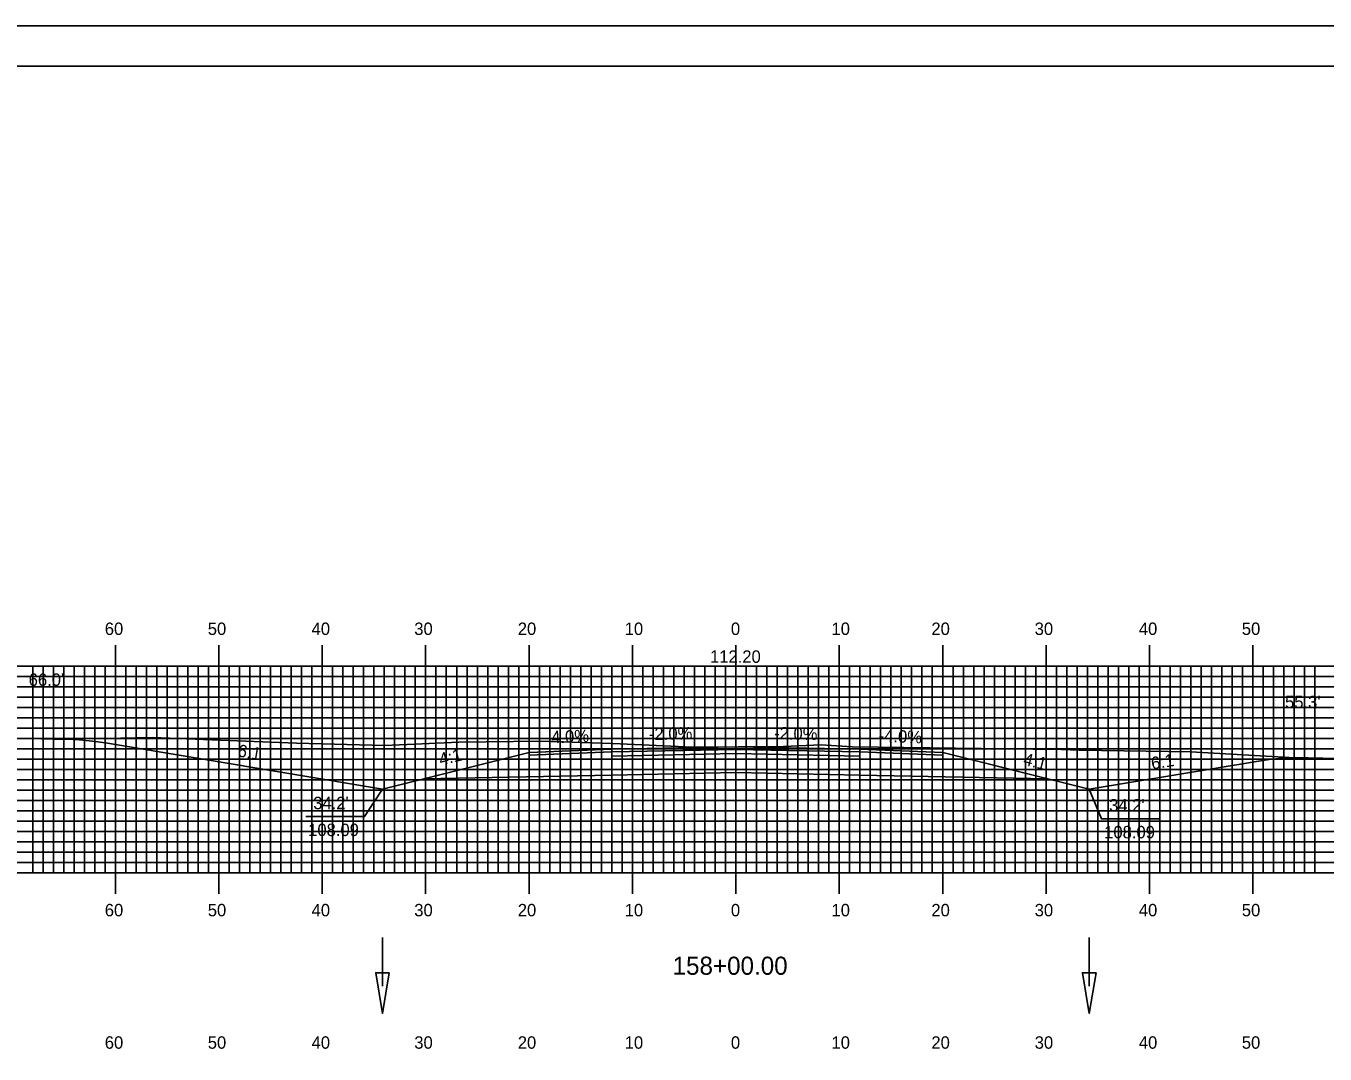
# Model space of a CAD drawing. Extents: x 1779499 to 1779842, y 442591 to 442811.
# Drawn here: x 1779596.2 to 1779721.8, y 442711.2 to 442810.5 of the extents above; entities that cross this region are included whole.
import ezdxf

# ---------------------------------------------------------------- set-up
doc = ezdxf.new("R2010")
doc.units = 0
for name, color, linetype in [('ANNOTATION', 7, 'Continuous'), ('BORDER', 7, 'Continuous'), ('D_Drainage_Ditch_Line', 7, 'Continuous'), ('D_Roadway_Centerline', 7, 'Continuous'), ('D_Roadway_Centerline_Text', 7, 'Continuous'), ('D_Roadway_Edge_Shoulder', 7, 'Continuous'), ('D_Roadway_Edge_TW', 7, 'Continuous'), ('D_Roadway_Pavement', 7, 'Continuous'), ('D_Roadway_SlopeLines', 7, 'Continuous'), ('D_Roadway_SubGrade', 7, 'Continuous'), ('D_Text_Standard', 7, 'Continuous'), ('H_V ANNOTATION', 7, 'Continuous'), ('MAJOR', 7, 'Continuous'), ('MINOR', 7, 'Continuous'), ('PLOT BOUNDARY', 7, 'Continuous'), ('S_Roadway_Centerline', 7, 'Continuous')]:
    doc.layers.add(name, color=color, linetype=linetype)

msp = doc.modelspace()

# ---------------------------------------------------------------- linework, layer by layer
at = {"layer": 'ANNOTATION'}
for points in [[(1779623.24, 442734.11), (1779628.93, 442734.11), (1779630.67, 442736.76)], [(1779705.9, 442733.88), (1779700.21, 442733.88), (1779699.02, 442736.76)]]:
    msp.add_lwpolyline(points, dxfattribs=at)
at = {"layer": 'BORDER'}
msp.add_lwpolyline([(1779515.24, 442596.67), (1779835.24, 442596.67), (1779835.24, 442806.67), (1779515.24, 442806.67)], close=True, dxfattribs=at)
at = {"layer": 'D_Drainage_Ditch_Line'}
for p, q in [((1779630.67, 442717.71), (1779630.67, 442722.41)), ((1779699.02, 442717.71), (1779699.02, 442722.41))]:
    msp.add_line(p, q, dxfattribs=at)
for points in [[(1779631.32, 442719.02), (1779630.01, 442719.02), (1779630.67, 442715.09)], [(1779699.67, 442719.02), (1779698.36, 442719.02), (1779699.02, 442715.09)]]:
    msp.add_lwpolyline(points, close=True, dxfattribs=at)
at = {"layer": 'D_Roadway_Centerline'}
msp.add_lwpolyline([(1779598.87, 442741.61), (1779600.12, 442741.6), (1779601.37, 442741.53), (1779602.62, 442741.41), (1779603.87, 442741.23), (1779630.67, 442736.76), (1779634.67, 442737.76), (1779644.84, 442740.3), (1779652.84, 442740.62), (1779664.84, 442740.86), (1779676.84, 442740.62), (1779684.84, 442740.3), (1779695.02, 442737.76), (1779699.02, 442736.76), (1779715.18, 442739.45), (1779716.43, 442739.63), (1779717.68, 442739.75), (1779718.93, 442739.8), (1779720.18, 442739.79)], dxfattribs=at)
at = {"layer": 'D_Roadway_Edge_Shoulder'}
for points in [[(1779652.84, 442740.62), (1779644.84, 442740.3), (1779644.84, 442740.05), (1779652.84, 442740.37)], [(1779676.84, 442740.62), (1779684.84, 442740.3), (1779684.84, 442740.05), (1779676.84, 442740.37)]]:
    msp.add_lwpolyline(points, close=True, dxfattribs=at)
at = {"layer": 'D_Roadway_Edge_TW'}
msp.add_lwpolyline([(1779652.84, 442740.37), (1779652.84, 442740.62), (1779664.84, 442740.86), (1779676.84, 442740.62), (1779676.84, 442740.37), (1779664.84, 442740.61)], close=True, dxfattribs=at)
at = {"layer": 'D_Roadway_Pavement'}
msp.add_lwpolyline([(1779652.84, 442739.96), (1779652.84, 442740.37), (1779664.84, 442740.61), (1779676.84, 442740.37), (1779676.84, 442739.96), (1779664.84, 442740.2)], close=True, dxfattribs=at)
at = {"layer": 'D_Roadway_SlopeLines'}
for points in [[(1779630.67, 442736.76), (1779603.87, 442741.23), (1779602.62, 442741.41), (1779601.37, 442741.53), (1779600.12, 442741.6), (1779598.87, 442741.61)], [(1779644.84, 442740.3), (1779630.67, 442736.76)], [(1779684.84, 442740.3), (1779699.02, 442736.76)], [(1779699.02, 442736.76), (1779715.18, 442739.45), (1779716.43, 442739.63), (1779717.68, 442739.75), (1779718.93, 442739.8), (1779720.18, 442739.79)]]:
    msp.add_lwpolyline(points, dxfattribs=at)
at = {"layer": 'D_Roadway_SubGrade'}
msp.add_lwpolyline([(1779652.84, 442738.12), (1779634.67, 442737.76), (1779644.84, 442740.3), (1779644.84, 442740.05), (1779652.84, 442740.37), (1779664.84, 442740.61), (1779676.84, 442740.37), (1779684.84, 442740.05), (1779684.84, 442740.3), (1779695.02, 442737.76), (1779676.84, 442738.12), (1779664.84, 442738.36)], close=True, dxfattribs=at)
at = {"layer": 'MAJOR'}
for p, q in [((1779604.84, 442750.67), (1779604.84, 442748.67)), ((1779614.84, 442750.67), (1779614.84, 442748.67)), ((1779624.84, 442750.67), (1779624.84, 442748.67)), ((1779634.84, 442750.67), (1779634.84, 442748.67)), ((1779644.84, 442750.67), (1779644.84, 442748.67)), ((1779654.84, 442750.67), (1779654.84, 442748.67)), ((1779664.84, 442750.67), (1779664.84, 442748.67)), ((1779674.84, 442750.67), (1779674.84, 442748.67)), ((1779684.84, 442750.67), (1779684.84, 442748.67)), ((1779694.84, 442750.67), (1779694.84, 442748.67)), ((1779704.84, 442750.67), (1779704.84, 442748.67)), ((1779714.84, 442750.67), (1779714.84, 442748.67)), ((1779524.84, 442748.67), (1779804.84, 442748.67)), ((1779524.84, 442748.67), (1779804.84, 442748.67)), ((1779604.84, 442728.67), (1779604.84, 442748.67)), ((1779614.84, 442728.67), (1779614.84, 442748.67)), ((1779624.84, 442728.67), (1779624.84, 442748.67)), ((1779634.84, 442728.67), (1779634.84, 442748.67)), ((1779644.84, 442728.67), (1779644.84, 442748.67)), ((1779654.84, 442728.67), (1779654.84, 442748.67)), ((1779664.84, 442728.67), (1779664.84, 442748.67)), ((1779674.84, 442728.67), (1779674.84, 442748.67)), ((1779684.84, 442728.67), (1779684.84, 442748.67)), ((1779694.84, 442728.67), (1779694.84, 442748.67)), ((1779704.84, 442728.67), (1779704.84, 442748.67)), ((1779714.84, 442728.67), (1779714.84, 442748.67)), ((1779524.84, 442743.67), (1779804.84, 442743.67)), ((1779524.84, 442738.67), (1779804.84, 442738.67)), ((1779524.84, 442733.67), (1779804.84, 442733.67)), ((1779524.84, 442728.67), (1779804.84, 442728.67)), ((1779524.84, 442728.67), (1779804.84, 442728.67)), ((1779604.84, 442726.66), (1779604.84, 442728.67)), ((1779614.84, 442726.66), (1779614.84, 442728.67)), ((1779624.84, 442726.66), (1779624.84, 442728.67)), ((1779634.84, 442726.66), (1779634.84, 442728.67)), ((1779644.84, 442726.66), (1779644.84, 442728.67)), ((1779654.84, 442726.66), (1779654.84, 442728.67)), ((1779664.84, 442726.66), (1779664.84, 442728.67)), ((1779674.84, 442726.66), (1779674.84, 442728.67)), ((1779684.84, 442726.66), (1779684.84, 442728.67)), ((1779694.84, 442726.66), (1779694.84, 442728.67)), ((1779704.84, 442726.66), (1779704.84, 442728.67)), ((1779714.84, 442726.66), (1779714.84, 442728.67))]:
    msp.add_line(p, q, dxfattribs=at)
at = {"layer": 'MINOR'}
for p, q in [((1779524.84, 442747.67), (1779804.84, 442747.67)), ((1779596.84, 442728.67), (1779596.84, 442748.67)), ((1779597.84, 442728.67), (1779597.84, 442748.67)), ((1779598.84, 442728.67), (1779598.84, 442748.67)), ((1779599.84, 442728.67), (1779599.84, 442748.67)), ((1779600.84, 442728.67), (1779600.84, 442748.67)), ((1779601.84, 442728.67), (1779601.84, 442748.67)), ((1779602.84, 442728.67), (1779602.84, 442748.67)), ((1779603.84, 442728.67), (1779603.84, 442748.67)), ((1779605.84, 442728.67), (1779605.84, 442748.67)), ((1779606.84, 442728.67), (1779606.84, 442748.67)), ((1779607.84, 442728.67), (1779607.84, 442748.67)), ((1779608.84, 442728.67), (1779608.84, 442748.67)), ((1779609.84, 442728.67), (1779609.84, 442748.67)), ((1779610.84, 442728.67), (1779610.84, 442748.67)), ((1779611.84, 442728.67), (1779611.84, 442748.67)), ((1779612.84, 442728.67), (1779612.84, 442748.67)), ((1779613.84, 442728.67), (1779613.84, 442748.67)), ((1779615.84, 442728.67), (1779615.84, 442748.67)), ((1779616.84, 442728.67), (1779616.84, 442748.67)), ((1779617.84, 442728.67), (1779617.84, 442748.67)), ((1779618.84, 442728.67), (1779618.84, 442748.67)), ((1779619.84, 442728.67), (1779619.84, 442748.67)), ((1779620.84, 442728.67), (1779620.84, 442748.67)), ((1779621.84, 442728.67), (1779621.84, 442748.67)), ((1779622.84, 442728.67), (1779622.84, 442748.67)), ((1779623.84, 442728.67), (1779623.84, 442748.67)), ((1779625.84, 442728.67), (1779625.84, 442748.67)), ((1779626.84, 442728.67), (1779626.84, 442748.67)), ((1779627.84, 442728.67), (1779627.84, 442748.67)), ((1779628.84, 442728.67), (1779628.84, 442748.67)), ((1779629.84, 442728.67), (1779629.84, 442748.67)), ((1779630.84, 442728.67), (1779630.84, 442748.67)), ((1779631.84, 442728.67), (1779631.84, 442748.67)), ((1779632.84, 442728.67), (1779632.84, 442748.67)), ((1779633.84, 442728.67), (1779633.84, 442748.67)), ((1779635.84, 442728.67), (1779635.84, 442748.67)), ((1779636.84, 442728.67), (1779636.84, 442748.67)), ((1779637.84, 442728.67), (1779637.84, 442748.67)), ((1779638.84, 442728.67), (1779638.84, 442748.67)), ((1779639.84, 442728.67), (1779639.84, 442748.67)), ((1779640.84, 442728.67), (1779640.84, 442748.67)), ((1779641.84, 442728.67), (1779641.84, 442748.67)), ((1779642.84, 442728.67), (1779642.84, 442748.67)), ((1779643.84, 442728.67), (1779643.84, 442748.67)), ((1779645.84, 442728.67), (1779645.84, 442748.67)), ((1779646.84, 442728.67), (1779646.84, 442748.67)), ((1779647.84, 442728.67), (1779647.84, 442748.67)), ((1779648.84, 442728.67), (1779648.84, 442748.67)), ((1779649.84, 442728.67), (1779649.84, 442748.67)), ((1779650.84, 442728.67), (1779650.84, 442748.67)), ((1779651.84, 442728.67), (1779651.84, 442748.67)), ((1779652.84, 442728.67), (1779652.84, 442748.67)), ((1779653.84, 442728.67), (1779653.84, 442748.67)), ((1779655.84, 442728.67), (1779655.84, 442748.67)), ((1779656.84, 442728.67), (1779656.84, 442748.67)), ((1779657.84, 442728.67), (1779657.84, 442748.67)), ((1779658.84, 442728.67), (1779658.84, 442748.67)), ((1779659.84, 442728.67), (1779659.84, 442748.67)), ((1779660.84, 442728.67), (1779660.84, 442748.67)), ((1779661.84, 442728.67), (1779661.84, 442748.67)), ((1779662.84, 442728.67), (1779662.84, 442748.67)), ((1779663.84, 442728.67), (1779663.84, 442748.67)), ((1779665.84, 442728.67), (1779665.84, 442748.67)), ((1779666.84, 442728.67), (1779666.84, 442748.67)), ((1779667.84, 442728.67), (1779667.84, 442748.67)), ((1779668.84, 442728.67), (1779668.84, 442748.67)), ((1779669.84, 442728.67), (1779669.84, 442748.67)), ((1779670.84, 442728.67), (1779670.84, 442748.67)), ((1779671.84, 442728.67), (1779671.84, 442748.67)), ((1779672.84, 442728.67), (1779672.84, 442748.67)), ((1779673.84, 442728.67), (1779673.84, 442748.67)), ((1779675.84, 442728.67), (1779675.84, 442748.67)), ((1779676.84, 442728.67), (1779676.84, 442748.67)), ((1779677.84, 442728.67), (1779677.84, 442748.67)), ((1779678.84, 442728.67), (1779678.84, 442748.67)), ((1779679.84, 442728.67), (1779679.84, 442748.67)), ((1779680.84, 442728.67), (1779680.84, 442748.67)), ((1779681.84, 442728.67), (1779681.84, 442748.67)), ((1779682.84, 442728.67), (1779682.84, 442748.67)), ((1779683.84, 442728.67), (1779683.84, 442748.67)), ((1779685.84, 442728.67), (1779685.84, 442748.67)), ((1779686.84, 442728.67), (1779686.84, 442748.67)), ((1779687.84, 442728.67), (1779687.84, 442748.67)), ((1779688.84, 442728.67), (1779688.84, 442748.67)), ((1779689.84, 442728.67), (1779689.84, 442748.67)), ((1779690.84, 442728.67), (1779690.84, 442748.67)), ((1779691.84, 442728.67), (1779691.84, 442748.67)), ((1779692.84, 442728.67), (1779692.84, 442748.67)), ((1779693.84, 442728.67), (1779693.84, 442748.67)), ((1779695.84, 442728.67), (1779695.84, 442748.67)), ((1779696.84, 442728.67), (1779696.84, 442748.67)), ((1779697.84, 442728.67), (1779697.84, 442748.67)), ((1779698.84, 442728.67), (1779698.84, 442748.67)), ((1779699.84, 442728.67), (1779699.84, 442748.67)), ((1779700.84, 442728.67), (1779700.84, 442748.67)), ((1779701.84, 442728.67), (1779701.84, 442748.67)), ((1779702.84, 442728.67), (1779702.84, 442748.67)), ((1779703.84, 442728.67), (1779703.84, 442748.67)), ((1779705.84, 442728.67), (1779705.84, 442748.67)), ((1779706.84, 442728.67), (1779706.84, 442748.67)), ((1779707.84, 442728.67), (1779707.84, 442748.67)), ((1779708.84, 442728.67), (1779708.84, 442748.67)), ((1779709.84, 442728.67), (1779709.84, 442748.67)), ((1779710.84, 442728.67), (1779710.84, 442748.67)), ((1779711.84, 442728.67), (1779711.84, 442748.67)), ((1779712.84, 442728.67), (1779712.84, 442748.67)), ((1779713.84, 442728.67), (1779713.84, 442748.67)), ((1779715.84, 442728.67), (1779715.84, 442748.67)), ((1779716.84, 442728.67), (1779716.84, 442748.67)), ((1779717.84, 442728.67), (1779717.84, 442748.67)), ((1779718.84, 442728.67), (1779718.84, 442748.67)), ((1779719.84, 442728.67), (1779719.84, 442748.67)), ((1779720.84, 442728.67), (1779720.84, 442748.67)), ((1779524.84, 442746.67), (1779804.84, 442746.67)), ((1779524.84, 442745.67), (1779804.84, 442745.67)), ((1779524.84, 442744.67), (1779804.84, 442744.67)), ((1779524.84, 442742.67), (1779804.84, 442742.67)), ((1779524.84, 442741.67), (1779804.84, 442741.67)), ((1779524.84, 442740.67), (1779804.84, 442740.67)), ((1779524.84, 442739.67), (1779804.84, 442739.67)), ((1779524.84, 442737.67), (1779804.84, 442737.67)), ((1779524.84, 442736.67), (1779804.84, 442736.67)), ((1779524.84, 442735.67), (1779804.84, 442735.67)), ((1779524.84, 442734.67), (1779804.84, 442734.67)), ((1779524.84, 442732.67), (1779804.84, 442732.67)), ((1779524.84, 442731.67), (1779804.84, 442731.67)), ((1779524.84, 442730.67), (1779804.84, 442730.67)), ((1779524.84, 442729.67), (1779804.84, 442729.67))]:
    msp.add_line(p, q, dxfattribs=at)
at = {"layer": 'PLOT BOUNDARY'}
msp.add_lwpolyline([(1779499.06, 442590.55), (1779839.06, 442590.55), (1779839.06, 442810.55), (1779499.06, 442810.55)], close=True, dxfattribs=at)
at = {"layer": 'S_Roadway_Centerline'}
msp.add_lwpolyline([(1779585.54, 442741.94), (1779598.93, 442741.61), (1779603.78, 442741.67), (1779608.46, 442741.77), (1779622.35, 442741.22), (1779630.9, 442741), (1779638.06, 442741.3), (1779645.99, 442741.42), (1779652.94, 442741.19), (1779660.66, 442740.83), (1779669.44, 442740.88), (1779673.08, 442741.04), (1779676.09, 442740.85), (1779693.59, 442740.62), (1779695.49, 442740.63), (1779698.05, 442740.55), (1779708.84, 442740.36), (1779718.34, 442739.83), (1779720, 442739.79), (1779721.59, 442739.75), (1779731.64, 442739.56)], dxfattribs=at)

# ---------------------------------------------------------------- texts
at = {"layer": 'ANNOTATION'}
for s, rotation, p in [('-4.0%', 2.2906, (1779646.47, 442741.17)), ('-2.0%', 1.1458, (1779656.45, 442741.5)), ('-2.0%', 358.8542, (1779668.53, 442741.59)), ('-4.0%', 357.7094, (1779678.63, 442741.35)), ('6:1', 350.5377, (1779616.6, 442739.93)), ('4:1', 14.0362, (1779636.29, 442739.03)), ('4:1', 345.9638, (1779692.56, 442739.13)), ('6:1', 9.4625, (1779705.1, 442738.65))]:
    msp.add_text(s, height=1.2, rotation=rotation, dxfattribs=at).set_placement(p)
for s, p in [("34.2'", (1779623.97, 442734.83)), ("34.2'", (1779700.94, 442734.61)), ('108.09', (1779623.48, 442732.23)), ('108.09', (1779700.46, 442732.01))]:
    msp.add_text(s, height=1.2, dxfattribs=at).set_placement(p)
at = {"layer": 'D_Roadway_Centerline'}
for s in ['C', 'L']:
    msp.add_text(s, height=0.0146, dxfattribs=at).set_placement((1779664.84, 442740.86))
at = {"layer": 'D_Roadway_Centerline_Text'}
msp.add_text('112.20', height=1.2, dxfattribs=at).set_placement((1779662.34, 442748.98))
at = {"layer": 'D_Text_Standard'}
for s, p in [("66.0'", (1779596.45, 442746.75)), ("55.3'", (1779717.95, 442744.59))]:
    msp.add_text(s, height=1.2, dxfattribs=at).set_placement(p)
at = {"layer": 'H_V ANNOTATION'}
for s, height, p in [('60', 1.2, (1779603.81, 442751.67)), ('50', 1.2, (1779613.77, 442751.67)), ('40', 1.2, (1779623.81, 442751.67)), ('30', 1.2, (1779633.74, 442751.67)), ('20', 1.2, (1779643.75, 442751.67)), ('10', 1.2, (1779654.09, 442751.67)), ('0', 1.2, (1779664.36, 442751.67)), ('10', 1.2, (1779674.09, 442751.67)), ('20', 1.2, (1779683.75, 442751.67)), ('30', 1.2, (1779693.74, 442751.67)), ('40', 1.2, (1779703.81, 442751.67)), ('50', 1.2, (1779713.77, 442751.67)), ('60', 1.2, (1779603.81, 442724.47)), ('50', 1.2, (1779613.77, 442724.47)), ('40', 1.2, (1779623.81, 442724.47)), ('30', 1.2, (1779633.74, 442724.47)), ('20', 1.2, (1779643.75, 442724.47)), ('10', 1.2, (1779654.09, 442724.47)), ('0', 1.2, (1779664.36, 442724.47)), ('10', 1.2, (1779674.09, 442724.47)), ('20', 1.2, (1779683.75, 442724.47)), ('30', 1.2, (1779693.74, 442724.47)), ('40', 1.2, (1779703.81, 442724.47)), ('50', 1.2, (1779713.77, 442724.47)), ('158+00.00', 1.75, (1779658.72, 442718.82)), ('60', 1.2, (1779603.81, 442711.67)), ('50', 1.2, (1779613.77, 442711.67)), ('40', 1.2, (1779623.81, 442711.67)), ('30', 1.2, (1779633.74, 442711.67)), ('20', 1.2, (1779643.75, 442711.67)), ('10', 1.2, (1779654.09, 442711.67)), ('0', 1.2, (1779664.36, 442711.67)), ('10', 1.2, (1779674.09, 442711.67)), ('20', 1.2, (1779683.75, 442711.67)), ('30', 1.2, (1779693.74, 442711.67)), ('40', 1.2, (1779703.81, 442711.67)), ('50', 1.2, (1779713.77, 442711.67))]:
    msp.add_text(s, height=height, dxfattribs=at).set_placement(p)

doc.saveas('drawing.dxf')
